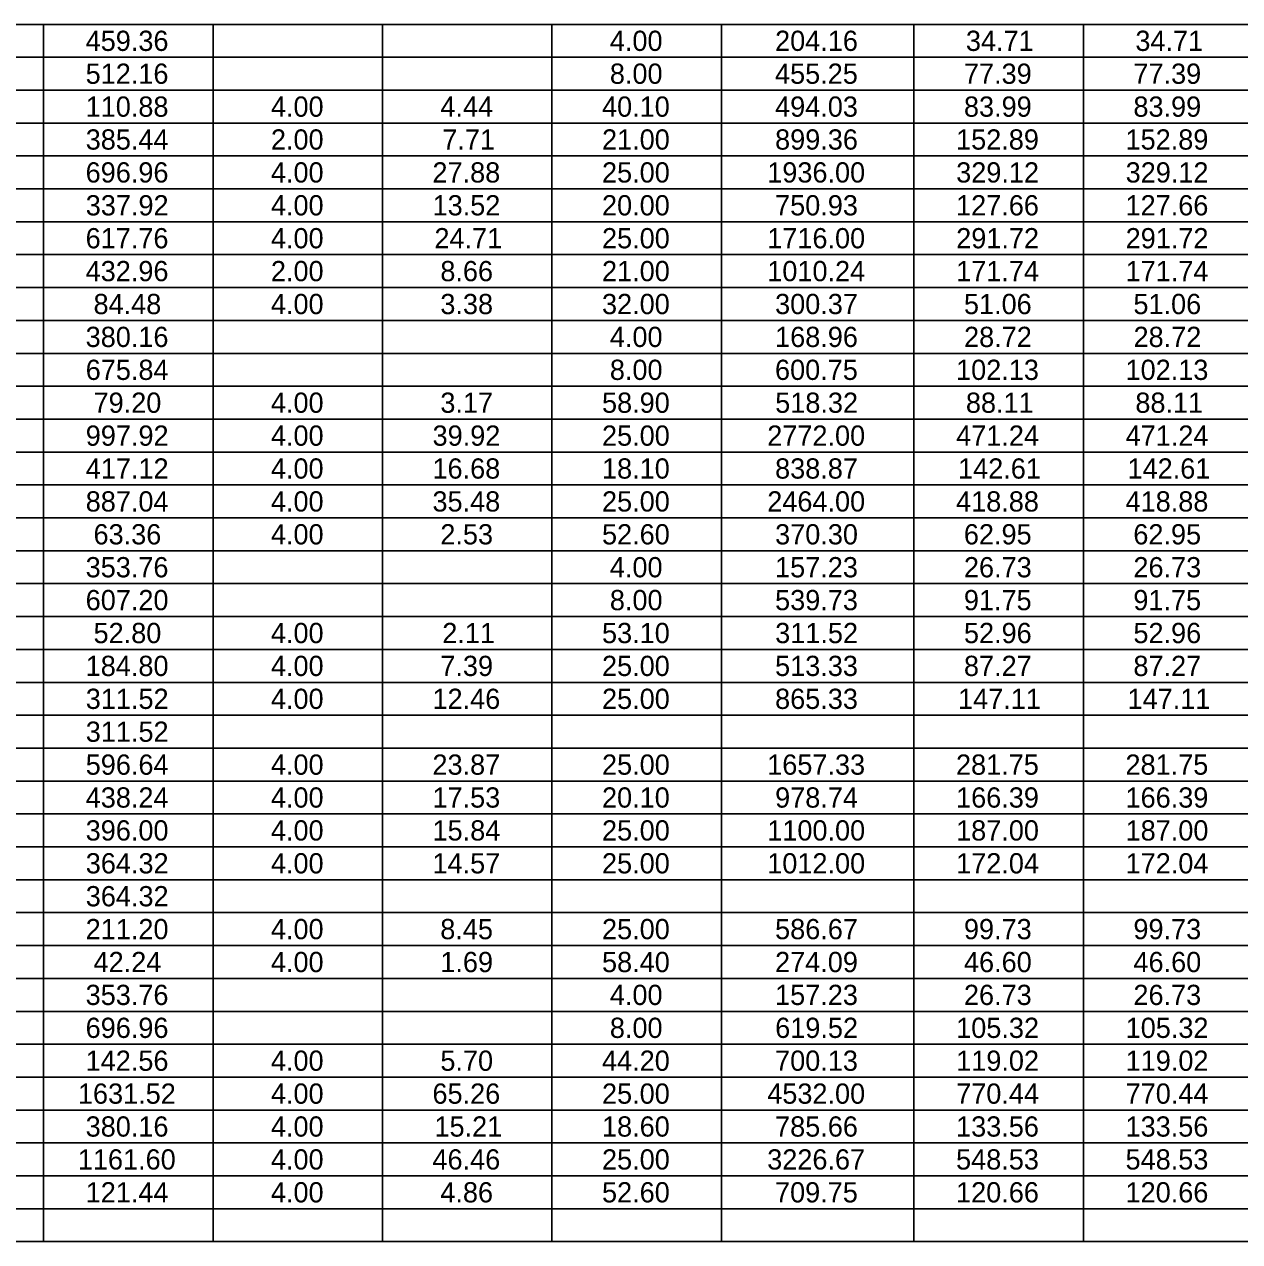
# Model space of a CAD drawing. Extents: x 2261867 to 2275370, y -3124789 to -3122260.
# Drawn here: x 2269764 to 2270088.1, y -3124227.7 to -3123903.1 of the extents above; entities that cross this region are included whole.
import ezdxf

# ---------------------------------------------------------------- set-up
doc = ezdxf.new("R2010")
doc.units = 0
doc.layers.add('Default', color=7, linetype='Continuous')

msp = doc.modelspace()

# ---------------------------------------------------------------- linework, layer by layer
at = {"layer": 'Default'}
for p, q in [((2269400.16, -3123903.07), (2270414.11, -3123903.07)), ((2269769.15, -3124210.19), (2269769.15, -3123903.07)), ((2269769.15, -3124227.74), (2269769.15, -3123903.07)), ((2269814.34, -3124218.97), (2269814.34, -3123903.07)), ((2269814.34, -3124227.74), (2269814.34, -3123903.07)), ((2269859.53, -3124218.97), (2269859.53, -3123903.07)), ((2269859.53, -3124227.74), (2269859.53, -3123903.07)), ((2269904.72, -3124201.42), (2269904.72, -3123903.07)), ((2269904.72, -3124227.74), (2269904.72, -3123903.07)), ((2269949.92, -3124201.42), (2269949.92, -3123903.07)), ((2269949.92, -3124227.74), (2269949.92, -3123903.07)), ((2270001.25, -3124227.74), (2270001.25, -3123903.07)), ((2270001.25, -3124227.74), (2270001.25, -3123903.07)), ((2270046.44, -3124227.74), (2270046.44, -3123903.07)), ((2270046.44, -3124227.74), (2270046.44, -3123903.07)), ((2269400.16, -3123911.84), (2270414.11, -3123911.84)), ((2269400.16, -3123920.62), (2270414.11, -3123920.62)), ((2269400.16, -3123929.39), (2270414.11, -3123929.39)), ((2269400.16, -3123938.17), (2270414.11, -3123938.17)), ((2269400.16, -3123946.94), (2270414.11, -3123946.94)), ((2269400.16, -3123955.72), (2270414.11, -3123955.72)), ((2269400.16, -3123964.49), (2270414.11, -3123964.49)), ((2269400.16, -3123973.27), (2270414.11, -3123973.27)), ((2269400.16, -3123982.04), (2270414.11, -3123982.04)), ((2269400.16, -3123990.82), (2270414.11, -3123990.82)), ((2269400.16, -3123999.59), (2270414.11, -3123999.59)), ((2269400.16, -3124008.37), (2270414.11, -3124008.37)), ((2269400.16, -3124017.14), (2270414.11, -3124017.14)), ((2269400.16, -3124025.92), (2270414.11, -3124025.92)), ((2269400.16, -3124034.69), (2270414.11, -3124034.69)), ((2269400.16, -3124043.47), (2270414.11, -3124043.47)), ((2269400.16, -3124052.24), (2270414.11, -3124052.24)), ((2269400.16, -3124061.02), (2270414.11, -3124061.02)), ((2269400.16, -3124069.79), (2270414.11, -3124069.79)), ((2269400.16, -3124078.57), (2270414.11, -3124078.57)), ((2269400.16, -3124087.34), (2270414.11, -3124087.34)), ((2269400.16, -3124096.12), (2270414.11, -3124096.12)), ((2269400.16, -3124104.89), (2270414.11, -3124104.89)), ((2269400.16, -3124113.67), (2270414.11, -3124113.67)), ((2269400.16, -3124122.44), (2270414.11, -3124122.44)), ((2269400.16, -3124131.22), (2270414.11, -3124131.22)), ((2269400.16, -3124139.99), (2270414.11, -3124139.99)), ((2269400.16, -3124148.77), (2270414.11, -3124148.77)), ((2269400.16, -3124157.54), (2270414.11, -3124157.54)), ((2269400.16, -3124166.32), (2270414.11, -3124166.32)), ((2269400.16, -3124175.09), (2270414.11, -3124175.09)), ((2269400.16, -3124183.87), (2270414.11, -3124183.87)), ((2269400.16, -3124192.64), (2270414.11, -3124192.64)), ((2269400.16, -3124201.42), (2270414.11, -3124201.42)), ((2269400.16, -3124210.19), (2270414.11, -3124210.19)), ((2269400.16, -3124218.97), (2269859.53, -3124218.97)), ((2269769.15, -3124227.74), (2269769.15, -3124218.97)), ((2269814.34, -3124218.97), (2269859.53, -3124218.97)), ((2269859.53, -3124218.97), (2269949.92, -3124218.97)), ((2269904.72, -3124218.97), (2269949.92, -3124218.97)), ((2269949.92, -3124218.97), (2270414.11, -3124218.97)), ((2269400.16, -3124227.74), (2270414.11, -3124227.74)), ((2269490.54, -3124227.74), (2269769.15, -3124227.74)), ((2269769.15, -3124227.74), (2269949.92, -3124227.74)), ((2269949.92, -3124227.74), (2270414.11, -3124227.74))]:
    msp.add_line(p, q, dxfattribs=at)

# ---------------------------------------------------------------- texts
for s, p in [('459.36', (2269780.38, -3123910.16)), ('4.00', (2269920.16, -3123910.16)), ('204.16', (2269964.22, -3123910.16)), ('34.71', (2270015.1, -3123910.16)), ('34.71', (2270060.29, -3123910.16)), ('512.16', (2269780.38, -3123918.93)), ('8.00', (2269920.16, -3123918.93)), ('455.25', (2269964.2, -3123918.93)), ('77.39', (2270014.58, -3123918.93)), ('77.39', (2270059.77, -3123918.93)), ('110.88', (2269780.38, -3123927.71)), ('4.00', (2269829.78, -3123927.71)), ('4.44', (2269874.97, -3123927.71)), ('40.10', (2269918.07, -3123927.71)), ('494.03', (2269964.22, -3123927.71)), ('83.99', (2270014.58, -3123927.71)), ('83.99', (2270059.77, -3123927.71)), ('385.44', (2269780.4, -3123936.48)), ('2.00', (2269829.78, -3123936.48)), ('7.71', (2269875.48, -3123936.48)), ('21.00', (2269918.07, -3123936.48)), ('899.36', (2269964.22, -3123936.48)), ('152.89', (2270012.48, -3123936.48)), ('152.89', (2270057.67, -3123936.48)), ('696.96', (2269780.38, -3123945.26)), ('4.00', (2269829.78, -3123945.26)), ('27.88', (2269872.86, -3123945.26)), ('25.00', (2269918.07, -3123945.26)), ('1936.00', (2269962.13, -3123945.26)), ('329.12', (2270012.51, -3123945.26)), ('329.12', (2270057.7, -3123945.26)), ('337.92', (2269780.41, -3123954.03)), ('4.00', (2269829.78, -3123954.03)), ('13.52', (2269872.89, -3123954.03)), ('20.00', (2269918.07, -3123954.03)), ('750.93', (2269964.22, -3123954.03)), ('127.66', (2270012.48, -3123954.03)), ('127.66', (2270057.67, -3123954.03)), ('617.76', (2269780.38, -3123962.81)), ('4.00', (2269829.78, -3123962.81)), ('24.71', (2269873.39, -3123962.81)), ('25.00', (2269918.07, -3123962.81)), ('1716.00', (2269962.13, -3123962.81)), ('291.72', (2270012.51, -3123962.81)), ('291.72', (2270057.7, -3123962.81)), ('432.96', (2269780.38, -3123971.58)), ('2.00', (2269829.78, -3123971.58)), ('8.66', (2269874.96, -3123971.58)), ('21.00', (2269918.07, -3123971.58)), ('1010.24', (2269962.14, -3123971.58)), ('171.74', (2270012.5, -3123971.58)), ('171.74', (2270057.69, -3123971.58)), ('84.48', (2269782.48, -3123980.36)), ('4.00', (2269829.78, -3123980.36)), ('3.38', (2269874.96, -3123980.36)), ('32.00', (2269918.07, -3123980.36)), ('300.37', (2269964.22, -3123980.36)), ('51.06', (2270014.58, -3123980.36)), ('51.06', (2270059.77, -3123980.36)), ('380.16', (2269780.38, -3123989.13)), ('4.00', (2269920.16, -3123989.13)), ('168.96', (2269964.22, -3123989.13)), ('28.72', (2270014.61, -3123989.13)), ('28.72', (2270059.8, -3123989.13)), ('675.84', (2269780.4, -3123997.91)), ('8.00', (2269920.16, -3123997.91)), ('600.75', (2269964.2, -3123997.91)), ('102.13', (2270012.48, -3123997.91)), ('102.13', (2270057.67, -3123997.91)), ('79.20', (2269782.49, -3124006.68)), ('4.00', (2269829.78, -3124006.68)), ('3.17', (2269874.96, -3124006.68)), ('58.90', (2269918.07, -3124006.68)), ('518.32', (2269964.25, -3124006.68)), ('88.11', (2270015.1, -3124006.68)), ('88.11', (2270060.29, -3124006.68)), ('997.92', (2269780.41, -3124015.46)), ('4.00', (2269829.78, -3124015.46)), ('39.92', (2269872.89, -3124015.46)), ('25.00', (2269918.07, -3124015.46)), ('2772.00', (2269962.13, -3124015.46)), ('471.24', (2270012.5, -3124015.46)), ('471.24', (2270057.69, -3124015.46)), ('417.12', (2269780.41, -3124024.23)), ('4.00', (2269829.78, -3124024.23)), ('16.68', (2269872.86, -3124024.23)), ('18.10', (2269918.07, -3124024.23)), ('838.87', (2269964.22, -3124024.23)), ('142.61', (2270013.01, -3124024.23)), ('142.61', (2270058.2, -3124024.23)), ('887.04', (2269780.4, -3124033.01)), ('4.00', (2269829.78, -3124033.01)), ('35.48', (2269872.86, -3124033.01)), ('25.00', (2269918.07, -3124033.01)), ('2464.00', (2269962.13, -3124033.01)), ('418.88', (2270012.48, -3124033.01)), ('418.88', (2270057.67, -3124033.01)), ('63.36', (2269782.48, -3124041.78)), ('4.00', (2269829.78, -3124041.78)), ('2.53', (2269874.96, -3124041.78)), ('52.60', (2269918.07, -3124041.78)), ('370.30', (2269964.23, -3124041.78)), ('62.95', (2270014.56, -3124041.78)), ('62.95', (2270059.75, -3124041.78)), ('353.76', (2269780.38, -3124050.56)), ('4.00', (2269920.16, -3124050.56)), ('157.23', (2269964.22, -3124050.56)), ('26.73', (2270014.58, -3124050.56)), ('26.73', (2270059.77, -3124050.56)), ('607.20', (2269780.39, -3124059.33)), ('8.00', (2269920.16, -3124059.33)), ('539.73', (2269964.22, -3124059.33)), ('91.75', (2270014.56, -3124059.33)), ('91.75', (2270059.75, -3124059.33)), ('52.80', (2269782.49, -3124068.11)), ('4.00', (2269829.78, -3124068.11)), ('2.11', (2269875.48, -3124068.11)), ('53.10', (2269918.07, -3124068.11)), ('311.52', (2269964.25, -3124068.11)), ('52.96', (2270014.58, -3124068.11)), ('52.96', (2270059.77, -3124068.11)), ('184.80', (2269780.39, -3124076.88)), ('4.00', (2269829.78, -3124076.88)), ('7.39', (2269874.96, -3124076.88)), ('25.00', (2269918.07, -3124076.88)), ('513.33', (2269964.22, -3124076.88)), ('87.27', (2270014.58, -3124076.88)), ('87.27', (2270059.77, -3124076.88)), ('311.52', (2269780.41, -3124085.66)), ('4.00', (2269829.78, -3124085.66)), ('12.46', (2269872.86, -3124085.66)), ('25.00', (2269918.07, -3124085.66)), ('865.33', (2269964.22, -3124085.66)), ('147.11', (2270013.01, -3124085.66)), ('147.11', (2270058.2, -3124085.66)), ('311.52', (2269780.41, -3124094.43)), ('596.64', (2269780.4, -3124103.21)), ('4.00', (2269829.78, -3124103.21)), ('23.87', (2269872.86, -3124103.21)), ('25.00', (2269918.07, -3124103.21)), ('1657.33', (2269962.12, -3124103.21)), ('281.75', (2270012.46, -3124103.21)), ('281.75', (2270057.65, -3124103.21)), ('438.24', (2269780.4, -3124111.98)), ('4.00', (2269829.78, -3124111.98)), ('17.53', (2269872.86, -3124111.98)), ('20.10', (2269918.07, -3124111.98)), ('978.74', (2269964.23, -3124111.98)), ('166.39', (2270012.48, -3124111.98)), ('166.39', (2270057.67, -3124111.98)), ('396.00', (2269780.39, -3124120.76)), ('4.00', (2269829.78, -3124120.76)), ('15.84', (2269872.88, -3124120.76)), ('25.00', (2269918.07, -3124120.76)), ('1100.00', (2269962.13, -3124120.76)), ('187.00', (2270012.49, -3124120.76)), ('187.00', (2270057.68, -3124120.76)), ('364.32', (2269780.41, -3124129.53)), ('4.00', (2269829.78, -3124129.53)), ('14.57', (2269872.86, -3124129.53)), ('25.00', (2269918.07, -3124129.53)), ('1012.00', (2269962.13, -3124129.53)), ('172.04', (2270012.5, -3124129.53)), ('172.04', (2270057.69, -3124129.53)), ('364.32', (2269780.41, -3124138.31)), ('211.20', (2269780.39, -3124147.08)), ('4.00', (2269829.78, -3124147.08)), ('8.45', (2269874.94, -3124147.08)), ('25.00', (2269918.07, -3124147.08)), ('586.67', (2269964.22, -3124147.08)), ('99.73', (2270014.58, -3124147.08)), ('99.73', (2270059.77, -3124147.08)), ('42.24', (2269782.49, -3124155.86)), ('4.00', (2269829.78, -3124155.86)), ('1.69', (2269874.96, -3124155.86)), ('58.40', (2269918.07, -3124155.86)), ('274.09', (2269964.22, -3124155.86)), ('46.60', (2270014.59, -3124155.86)), ('46.60', (2270059.78, -3124155.86)), ('353.76', (2269780.38, -3124164.63)), ('4.00', (2269920.16, -3124164.63)), ('157.23', (2269964.22, -3124164.63)), ('26.73', (2270014.58, -3124164.63)), ('26.73', (2270059.77, -3124164.63)), ('696.96', (2269780.38, -3124173.41)), ('8.00', (2269920.16, -3124173.41)), ('619.52', (2269964.25, -3124173.41)), ('105.32', (2270012.51, -3124173.41)), ('105.32', (2270057.7, -3124173.41)), ('142.56', (2269780.38, -3124182.18)), ('4.00', (2269829.78, -3124182.18)), ('5.70', (2269874.97, -3124182.18)), ('44.20', (2269918.07, -3124182.18)), ('700.13', (2269964.22, -3124182.18)), ('119.02', (2270012.51, -3124182.18)), ('119.02', (2270057.7, -3124182.18)), ('1631.52', (2269778.32, -3124190.96)), ('4.00', (2269829.78, -3124190.96)), ('65.26', (2269872.86, -3124190.96)), ('25.00', (2269918.07, -3124190.96)), ('4532.00', (2269962.13, -3124190.96)), ('770.44', (2270012.5, -3124190.96)), ('770.44', (2270057.69, -3124190.96)), ('380.16', (2269780.38, -3124199.73)), ('4.00', (2269829.78, -3124199.73)), ('15.21', (2269873.39, -3124199.73)), ('18.60', (2269918.07, -3124199.73)), ('785.66', (2269964.22, -3124199.73)), ('133.56', (2270012.48, -3124199.73)), ('133.56', (2270057.67, -3124199.73)), ('1161.60', (2269778.3, -3124208.51)), ('4.00', (2269829.78, -3124208.51)), ('46.46', (2269872.86, -3124208.51)), ('25.00', (2269918.07, -3124208.51)), ('3226.67', (2269962.12, -3124208.51)), ('548.53', (2270012.48, -3124208.51)), ('548.53', (2270057.67, -3124208.51)), ('121.44', (2269780.4, -3124217.28)), ('4.00', (2269829.78, -3124217.28)), ('4.86', (2269874.96, -3124217.28)), ('52.60', (2269918.07, -3124217.28)), ('709.75', (2269964.2, -3124217.28)), ('120.66', (2270012.48, -3124217.28)), ('120.66', (2270057.67, -3124217.28))]:
    msp.add_text(s, height=5.4, dxfattribs=at).set_placement(p)

doc.saveas('drawing.dxf')
